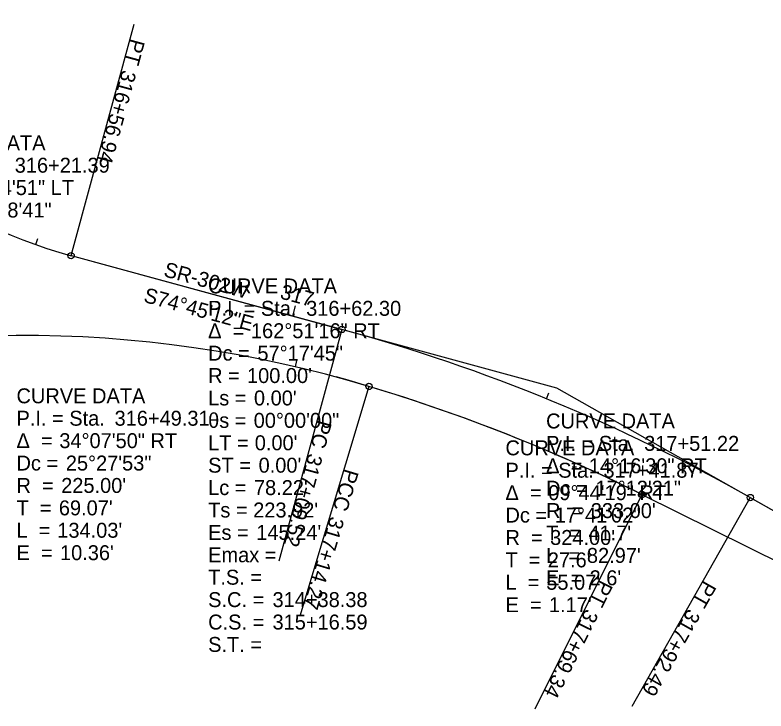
# Model space of a CAD drawing. Extents: x 2047151 to 2048731, y 456453 to 457874.
# Drawn here: x 2047750.5 to 2047891.2, y 456908.9 to 457039.3 of the extents above; entities that cross this region are included whole.
import ezdxf

# ---------------------------------------------------------------- set-up
doc = ezdxf.new("R2010")
doc.units = 0
for name, color, linetype in [('GE_P_Alignment', 7, 'Continuous'), ('GE_P_Alignment_100_Bearings', 7, 'Continuous'), ('GE_P_Alignment_100_Cardinal_Points', 7, 'Continuous'), ('GE_P_Alignment_100_Curve_Data', 7, 'Continuous'), ('GE_P_Alignment_100_Distances', 7, 'Continuous'), ('GE_P_Alignment_100_Stations', 7, 'Continuous'), ('GE_P_Alignment_500_Cardinal_Points', 7, 'Continuous'), ('GE_P_Alignment_500_Curve_Data', 7, 'Continuous'), ('GE_P_Alignment_500_Stations', 7, 'Continuous')]:
    doc.layers.add(name, color=color, linetype=linetype)

msp = doc.modelspace()

# ---------------------------------------------------------------- linework, layer by layer
at = {"layer": 'GE_P_Alignment'}
for p, q in [((2047761, 456994.22), (2047851.96, 456969.42)), ((2047761, 456994.22), (2047811.73, 456980.39)), ((2047851.96, 456969.42), (2048122.29, 456816.34)), ((2047867.94, 456949.46), (2048073.45, 456847.09)), ((2047867.94, 456949.46), (2048073.45, 456847.09)), ((2047888.25, 456948.87), (2047983.86, 456894.73))]:
    msp.add_line(p, q, dxfattribs=at)
for centre, radius, start, end in [((2047785.98, 457085.87), 95, 209.339, 254.7532), ((2047785.98, 457085.87), 95, 209.339, 254.7532), ((2047724.16, 456659.11), 333, 60.4781, 74.7532), ((2047724.16, 456659.11), 333, 60.4781, 74.7532), ((2047752, 456754.25), 225, 73.2611, 107.3917), ((2047752, 456754.25), 225, 73.2611, 107.3917), ((2047723.49, 456659.44), 324, 63.5225, 74.3965), ((2047723.49, 456659.44), 324, 63.5225, 73.2611), ((2047723.49, 456659.44), 324, 63.5225, 73.2611)]:
    msp.add_arc(centre, radius, start, end, dxfattribs=at)
at = {"layer": 'GE_P_Alignment_100_Cardinal_Points'}
for p, q in [((2047761, 456994.22), (2047772.83, 457037.63)), ((2047811.73, 456980.39), (2047799.9, 456936.97)), ((2047888.25, 456948.87), (2047866.08, 456909.72))]:
    msp.add_line(p, q, dxfattribs=at)
for centre in [(2047761, 456994.22), (2047811.73, 456980.39), (2047888.25, 456948.87)]:
    msp.add_circle(centre, 0.6, dxfattribs=at)
at = {"layer": 'GE_P_Alignment_100_Stations'}
for p, q in [((2047754.38, 456996.28), (2047754.78, 456997.42)), ((2047802.54, 456982.89), (2047803.07, 456984.82)), ((2047850.04, 456967.4), (2047850.5, 456968.51))]:
    msp.add_line(p, q, dxfattribs=at)
at = {"layer": 'GE_P_Alignment_500_Cardinal_Points'}
for p, q in [((2047816.81, 456969.71), (2047803.85, 456926.62)), ((2047867.94, 456949.46), (2047847.88, 456909.18))]:
    msp.add_line(p, q, dxfattribs=at)
for centre in [(2047816.81, 456969.71), (2047867.94, 456949.46)]:
    msp.add_circle(centre, 0.6, dxfattribs=at)
at = {"layer": 'GE_P_Alignment_500_Stations'}
msp.add_line((2047803.02, 456973.39), (2047803.29, 456974.56), dxfattribs=at)

# ---------------------------------------------------------------- texts
at = {"layer": 'GE_P_Alignment_100_Bearings'}
msp.add_text('S74°45\'12"E', height=2.8, rotation=344.7532, dxfattribs=at).set_placement((2047774.42, 456985.58))
at = {"layer": 'GE_P_Alignment_100_Cardinal_Points'}
for s, rotation, p in [('PT', 254.7532, (2047772.17, 457035.03)), ('316+56.94', 254.7532, (2047770.57, 457029.16)), ('PC', 254.7532, (2047807.19, 456963.56)), ('317+09.52', 254.7532, (2047805.48, 456957.27)), ('PT', 240.4781, (2047879.58, 456933.48)), ('317+92.49', 240.4781, (2047876.58, 456928.18))]:
    msp.add_text(s, height=2.8, rotation=rotation, dxfattribs=at).set_placement(p)
at = {"layer": 'GE_P_Alignment_100_Curve_Data'}
for s, p in [('CURVE DATA', (2047732.08, 457013.97)), ('316+21.39', (2047750.45, 457009.77)), ('45°24\'51" LT', (2047740.1, 457005.57)), ('60°18\'41"', (2047741.32, 457001.37)), ('CURVE DATA', (2047849.99, 456961.83)), ('P.I. = Sta. ', (2047849.99, 456957.63)), ('317+51.22', (2047868.36, 456957.63)), ('Δ  = ', (2047849.99, 456953.43)), ('14°16\'30" RT', (2047858.01, 456953.43)), ('Dc = ', (2047849.99, 456949.23)), ('17°12\'21"', (2047859.23, 456949.23)), ('R  = ', (2047849.99, 456945.03)), ("333.00'", (2047858.36, 456945.03)), ('T  = ', (2047849.99, 456940.83)), ("41.7'", (2047857.92, 456940.83)), ('L  = ', (2047849.99, 456936.63)), ("82.97'", (2047857.64, 456936.63)), ('E  = ', (2047849.99, 456932.43)), ("2.6'", (2047858.14, 456932.43))]:
    msp.add_text(s, height=2.8, dxfattribs=at).set_placement(p)
at = {"layer": 'GE_P_Alignment_100_Distances'}
msp.add_text('SR-302W', height=2.8, rotation=344.7532, dxfattribs=at).set_placement((2047778.18, 456990.39))
at = {"layer": 'GE_P_Alignment_100_Stations'}
msp.add_text('317', height=2.8, rotation=344.7532, dxfattribs=at).set_placement((2047799.99, 456986.23))
at = {"layer": 'GE_P_Alignment_500_Cardinal_Points'}
for s, rotation, p in [('PCC', 253.2611, (2047812.26, 456954.42)), ('317+14.27', 253.2611, (2047809.56, 456945.47)), ('PT', 243.5225, (2047860.1, 456933.61)), ('317+69.34', 243.5225, (2047857.39, 456928.16))]:
    msp.add_text(s, height=2.8, rotation=rotation, dxfattribs=at).set_placement(p)
at = {"layer": 'GE_P_Alignment_500_Curve_Data'}
for s, p in [('CURVE DATA', (2047786.68, 456987.14)), ('P.I. = Sta. ', (2047786.68, 456982.94)), ('316+62.30', (2047805.04, 456982.94)), ('Δ  = ', (2047786.68, 456978.74)), ('162°51\'16" RT', (2047794.7, 456978.74)), ('Dc = ', (2047786.68, 456974.54)), ('57°17\'45"', (2047795.91, 456974.54)), ('R = ', (2047786.68, 456970.34)), ("100.00'", (2047793.96, 456970.34)), ('CURVE DATA', (2047750.78, 456966.54)), ('Ls = ', (2047786.68, 456966.14)), ("0.00'", (2047795.26, 456966.14)), ('P.I. = Sta. ', (2047750.78, 456962.34)), ('316+49.31', (2047769.15, 456962.34)), ('θs = ', (2047786.68, 456961.94)), ('00°00\'00"', (2047795.21, 456961.94)), ('34°07\'50" RT', (2047758.8, 456958.14)), ('Δ  = ', (2047750.78, 456958.14)), ('LT = ', (2047786.68, 456957.74)), ("0.00'", (2047795.41, 456957.74)), ('CURVE DATA', (2047842.38, 456956.79)), ('25°27\'53"', (2047760.02, 456953.94)), ('Dc = ', (2047750.78, 456953.94)), ('ST = ', (2047786.68, 456953.54)), ("0.00'", (2047796.13, 456953.54)), ('P.I. = Sta. ', (2047842.38, 456952.59)), ('317+41.87', (2047860.74, 456952.59)), ('R  = ', (2047750.78, 456949.74)), ("225.00'", (2047759.15, 456949.74)), ('Lc = ', (2047786.68, 456949.34)), ("78.22'", (2047795.26, 456949.34)), ('Δ  = ', (2047842.38, 456948.39)), ('09°44\'19" RT', (2047850.4, 456948.39)), ('T  = ', (2047750.78, 456945.54)), ("69.07'", (2047758.71, 456945.54)), ('Ts = ', (2047786.68, 456945.14)), ("223.92'", (2047795.12, 456945.14)), ('Dc = ', (2047842.38, 456944.19)), ('17°41\'02"', (2047851.61, 456944.19)), ('L  = ', (2047750.78, 456941.34)), ("134.03'", (2047758.42, 456941.34)), ('Es = ', (2047786.68, 456940.94)), ("145.24'", (2047795.7, 456940.94)), ('R  = ', (2047842.38, 456939.99)), ("324.00'", (2047850.74, 456939.99)), ('E  = ', (2047750.78, 456937.14)), ("10.36'", (2047758.93, 456937.14)), ('Emax = ', (2047786.68, 456936.74)), ('T  = ', (2047842.38, 456935.79)), ("27.6'", (2047850.31, 456935.79)), ('T.S. = ', (2047786.68, 456932.54)), ('L  = ', (2047842.38, 456931.59)), ("55.07'", (2047850.02, 456931.59)), ('S.C. = ', (2047786.68, 456928.34)), ('314+38.38', (2047798.74, 456928.34)), ('E  = ', (2047842.38, 456927.39)), ("1.17'", (2047850.53, 456927.39)), ('C.S. = ', (2047786.68, 456924.14)), ('315+16.59', (2047798.74, 456924.14)), ('S.T. = ', (2047786.68, 456919.94))]:
    msp.add_text(s, height=2.8, dxfattribs=at).set_placement(p)

doc.saveas('drawing.dxf')
